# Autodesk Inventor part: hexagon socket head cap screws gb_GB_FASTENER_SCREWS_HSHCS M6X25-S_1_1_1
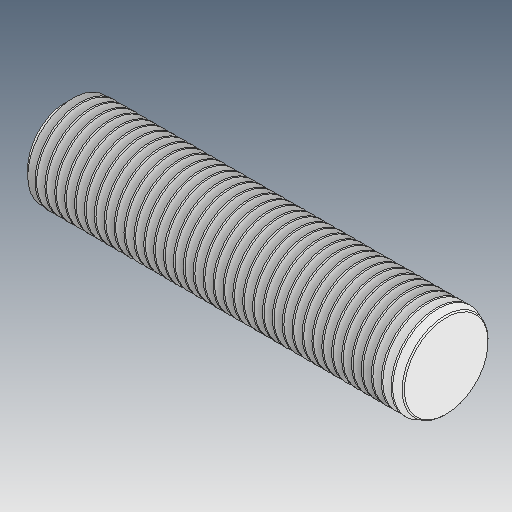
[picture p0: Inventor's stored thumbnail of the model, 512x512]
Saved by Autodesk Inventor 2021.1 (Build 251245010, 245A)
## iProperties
Created: 2021-05
Part Number: hexagon socket head cap screws gb_GB_FASTENER_SCREWS_HSHCS M6X25-S_1_1_1
Material: Ogólny
Document SubType Name: Modeling
Designer: user
Density: 1 g/cm^3
Appearance: Domyślna
Author: user
Revision Number: ÈÎºÎ
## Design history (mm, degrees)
feature "ÊäÈë1"
node "Bryła1"
